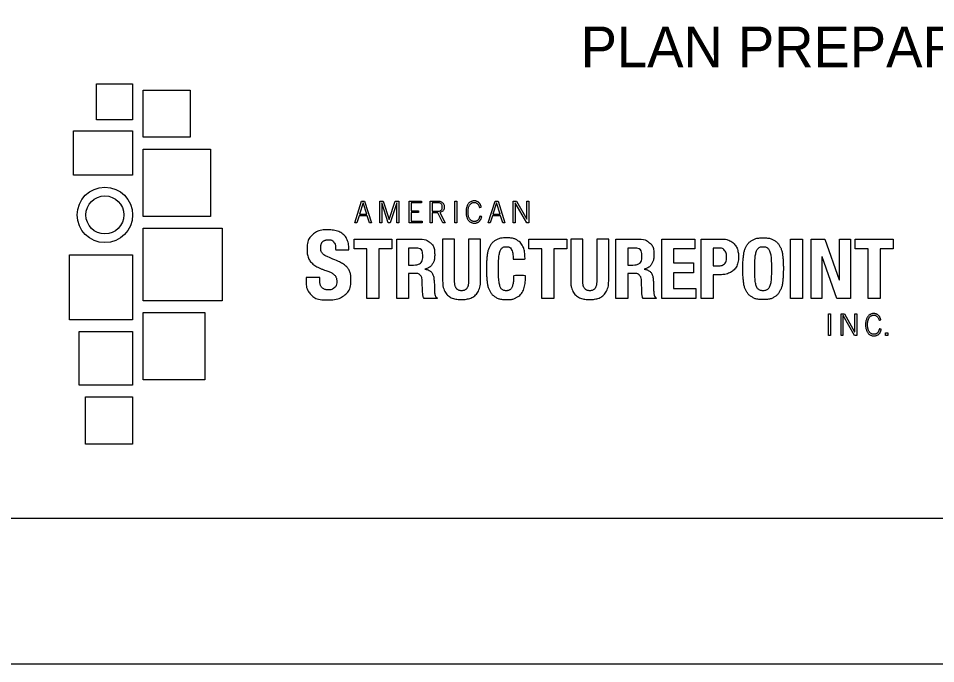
# Model space of a CAD drawing. Extents: x -21.9 to 47.3, y 14.1 to 48.7.
# Drawn here: x 1.676 to 4.831, y 26.733 to 28.955 of the extents above; entities that cross this region are included whole.
import ezdxf

# ---------------------------------------------------------------- set-up
doc = ezdxf.new("R2010")
doc.units = 0
for name, color, linetype in [('Default', 7, 'Continuous'), ('SH_Border', 7, 'Continuous'), ('SH_Cut_Line', 7, 'Continuous'), ('SH_Data', 7, 'Continuous'), ('SH_Text', 7, 'Continuous')]:
    doc.layers.add(name, color=color, linetype=linetype)

msp = doc.modelspace()

# ---------------------------------------------------------------- linework, layer by layer
at = {"layer": 'Default'}
for points in [[(1.944, 28.7301), (2.0687, 28.7301), (2.0687, 28.6054), (1.944, 28.6054)], [(2.1051, 28.7078), (2.2672, 28.7078), (2.2672, 28.5457), (2.1051, 28.5457)], [(1.8658, 28.5676), (2.0687, 28.5676), (2.0687, 28.4148), (1.8658, 28.4148)], [(2.1051, 28.5051), (2.3371, 28.5051), (2.3371, 28.2731), (2.1051, 28.2731)], [(2.1051, 28.2325), (2.3773, 28.2325), (2.3773, 27.983), (2.1051, 27.983)], [(1.8512, 28.1411), (2.0687, 28.1411), (2.0687, 27.9166), (1.8512, 27.9166)], [(2.1051, 27.9423), (2.3177, 27.9423), (2.3177, 27.7103), (2.1051, 27.7103)], [(1.8846, 27.8768), (2.0687, 27.8768), (2.0687, 27.6927), (1.8846, 27.6927)], [(1.9066, 27.6516), (2.0687, 27.6516), (2.0687, 27.4895), (1.9066, 27.4895)]]:
    msp.add_lwpolyline(points, close=True, dxfattribs=at)
for radius in [0.0954, 0.0654]:
    msp.add_circle((1.9733, 28.2783), radius, dxfattribs=at)
at = {"layer": 'SH_Border'}
msp.add_lwpolyline([(1.5, 48.2334), (33.5, 48.2334), (33.5, 27.2334), (1.5, 27.2334)], close=True, dxfattribs=at)
at = {"layer": 'SH_Cut_Line'}
msp.add_lwpolyline([(0, 26.7334), (34, 26.7334), (34, 48.7334), (0, 48.7334)], close=True, dxfattribs=at)
at = {"layer": 'SH_Data'}
for points in [[(2.8326, 28.2512), (2.8564, 28.3257), (2.8668, 28.3257), (2.8903, 28.2512), (2.8831, 28.2512), (2.8756, 28.2756), (2.8475, 28.2756), (2.8398, 28.2512), (2.8326, 28.2512)], [(2.8492, 28.2812), (2.8741, 28.2812), (2.8617, 28.3201), (2.8615, 28.3201), (2.8492, 28.2812)], [(2.9187, 28.2512), (2.9187, 28.3257), (2.9307, 28.3257), (2.9513, 28.2626), (2.9515, 28.2626), (2.9721, 28.3257), (2.9841, 28.3257), (2.9841, 28.2512), (2.9773, 28.2512), (2.9773, 28.3201), (2.9771, 28.3201), (2.9547, 28.2512), (2.9482, 28.2512), (2.9258, 28.3201), (2.9255, 28.3201), (2.9255, 28.2512), (2.9187, 28.2512)], [(3.02, 28.2512), (3.02, 28.3257), (3.0625, 28.3257), (3.0625, 28.32), (3.0268, 28.32), (3.0268, 28.2927), (3.0525, 28.2927), (3.0525, 28.2871), (3.0268, 28.2871), (3.0268, 28.2568), (3.0644, 28.2568), (3.0644, 28.2512), (3.02, 28.2512)], [(3.1254, 28.2865), (3.1436, 28.2512), (3.1362, 28.2512), (3.1189, 28.2852), (3.0996, 28.2852), (3.0996, 28.2512), (3.0928, 28.2512), (3.0928, 28.3257), (3.118, 28.3257)], [(3.0996, 28.32), (3.0996, 28.2908), (3.118, 28.2908)], [(3.118, 28.32), (3.0996, 28.32)], [(3.1777, 28.3257), (3.1845, 28.3257), (3.1845, 28.2512), (3.1777, 28.2512), (3.1777, 28.3257)], [(3.2918, 28.2512), (3.3157, 28.3257), (3.3261, 28.3257), (3.3496, 28.2512), (3.3423, 28.2512), (3.3348, 28.2756), (3.3067, 28.2756), (3.2991, 28.2512), (3.2918, 28.2512)], [(3.3084, 28.2812), (3.3333, 28.2812), (3.3209, 28.3201), (3.3207, 28.3201), (3.3084, 28.2812)], [(3.378, 28.3257), (3.3894, 28.3257), (3.4249, 28.2636), (3.4251, 28.2636), (3.4251, 28.3257), (3.4319, 28.3257), (3.4319, 28.2512), (3.4248, 28.2512), (3.385, 28.3201), (3.3847, 28.3201), (3.3847, 28.2512), (3.378, 28.2512), (3.378, 28.3257)], [(2.9607, 28.1949), (2.9607, 28.161), (2.916, 28.161), (2.916, 27.9907), (2.875, 27.9907), (2.875, 28.161), (2.8304, 28.161), (2.8304, 28.1949), (2.9607, 28.1949)], [(2.9771, 27.9907), (2.9771, 28.1949), (3.0534, 28.1949)], [(3.5622, 28.1949), (3.5622, 28.161), (3.5175, 28.161), (3.5175, 27.9907), (3.4765, 27.9907), (3.4765, 28.161), (3.4318, 28.161), (3.4318, 28.1949), (3.5622, 28.1949)], [(3.7311, 27.9907), (3.7311, 28.1949), (3.8074, 28.1949)], [(4.0029, 28.1949), (4.0029, 28.161), (3.9299, 28.161), (3.9299, 28.1133), (3.9986, 28.1133), (3.9986, 28.0794), (3.9299, 28.0794), (3.9299, 28.0246), (4.0058, 28.0246), (4.0058, 27.9907), (3.8889, 27.9907), (3.8889, 28.1949), (4.0029, 28.1949)], [(4.0251, 27.9907), (4.0251, 28.1949), (4.0971, 28.1949)], [(4.3319, 27.9907), (4.3319, 28.1949), (4.373, 28.1949), (4.373, 27.9907), (4.3319, 27.9907)], [(4.4499, 28.1949), (4.4997, 28.055), (4.5003, 28.055), (4.5003, 28.1949), (4.5379, 28.1949), (4.5379, 27.9907), (4.491, 27.9907), (4.4406, 28.1337), (4.4401, 28.1337), (4.4401, 27.9907), (4.4025, 27.9907), (4.4025, 28.1949), (4.4499, 28.1949)], [(4.6849, 28.1949), (4.6849, 28.161), (4.6402, 28.161), (4.6402, 27.9907), (4.5992, 27.9907), (4.5992, 28.161), (4.5546, 28.161), (4.5546, 28.1949), (4.6849, 28.1949)], [(3.0181, 28.1644), (3.0181, 28.1057), (3.0355, 28.1057)], [(3.0378, 28.1644), (3.0181, 28.1644)], [(3.7722, 28.1644), (3.7722, 28.1057), (3.7896, 28.1057)], [(3.7919, 28.1644), (3.7722, 28.1644)], [(4.0662, 28.1644), (4.0662, 28.1028), (4.0845, 28.1028)], [(4.0834, 28.1644), (4.0662, 28.1644)], [(3.0739, 28.0919), (3.0739, 28.0914)], [(3.828, 28.0919), (3.828, 28.0914)], [(3.0405, 28.077), (3.0181, 28.077), (3.0181, 27.9907), (2.9771, 27.9907)], [(3.7945, 28.077), (3.7722, 28.077), (3.7722, 27.9907), (3.7311, 27.9907)], [(4.0882, 28.0723), (4.0662, 28.0723), (4.0662, 27.9907), (4.0251, 27.9907)], [(3.0663, 28.0121), (3.0652, 28.0513)], [(3.8204, 28.0121), (3.8192, 28.0513)], [(3.1161, 27.9924), (3.1161, 27.9907), (3.0715, 27.9907)], [(3.8701, 27.9924), (3.8701, 27.9907), (3.8255, 27.9907)], [(4.4623, 27.9376), (4.4691, 27.9376), (4.4691, 27.8632), (4.4623, 27.8632), (4.4623, 27.9376)], [(4.5057, 27.9376), (4.5172, 27.9376), (4.5526, 27.8756), (4.5529, 27.8756), (4.5529, 27.9376), (4.5596, 27.9376), (4.5596, 27.8632), (4.5526, 27.8632), (4.5127, 27.9321), (4.5125, 27.9321), (4.5125, 27.8632), (4.5057, 27.8632), (4.5057, 27.9376)], [(4.6582, 27.8632), (4.6582, 27.8725), (4.667, 27.8725), (4.667, 27.8632), (4.6582, 27.8632)]]:
    msp.add_lwpolyline(points, dxfattribs=at)
for points in [[(3.118, 28.3257), (3.1253, 28.3257), (3.131, 28.3238), (3.1349, 28.3201), (3.1389, 28.3165), (3.1409, 28.3116), (3.1409, 28.3054), (3.1409, 28.3005), (3.1396, 28.2964), (3.1371, 28.2933), (3.1347, 28.2901), (3.1307, 28.2879), (3.1254, 28.2865)], [(3.118, 28.2908), (3.1229, 28.2908), (3.1268, 28.2921), (3.1297, 28.2947), (3.1326, 28.2973), (3.1341, 28.3008), (3.1341, 28.3054), (3.1341, 28.31), (3.1327, 28.3136), (3.13, 28.3162), (3.1274, 28.3188), (3.1233, 28.32), (3.118, 28.32)], [(3.2619, 28.3038), (3.2603, 28.3093), (3.258, 28.3135), (3.255, 28.3165), (3.2521, 28.3195), (3.2483, 28.321), (3.2438, 28.321), (3.2401, 28.321), (3.2369, 28.3202), (3.2342, 28.3185), (3.2316, 28.3168), (3.2294, 28.3145), (3.2276, 28.3115), (3.2259, 28.3086), (3.2246, 28.3051), (3.2238, 28.3011), (3.2229, 28.2972), (3.2225, 28.2929), (3.2225, 28.2884), (3.2225, 28.2838), (3.2229, 28.2796), (3.2238, 28.2756), (3.2246, 28.2716), (3.2259, 28.2682), (3.2277, 28.2652), (3.2295, 28.2623), (3.2318, 28.26), (3.2345, 28.2583), (3.2373, 28.2566), (3.2406, 28.2558), (3.2445, 28.2558), (3.2474, 28.2558), (3.25, 28.2563), (3.2521, 28.2572), (3.2541, 28.2582), (3.2559, 28.2596), (3.2574, 28.2612), (3.2588, 28.2629), (3.26, 28.2648), (3.2609, 28.267), (3.2618, 28.2692), (3.2626, 28.2715), (3.2632, 28.2739), (3.2632, 28.2739), (3.2696, 28.2728), (3.2696, 28.2728), (3.2689, 28.2695), (3.268, 28.2664), (3.2667, 28.2636), (3.2654, 28.2609), (3.2638, 28.2585), (3.2618, 28.2565), (3.2598, 28.2545), (3.2574, 28.2529), (3.2545, 28.2518), (3.2517, 28.2507), (3.2483, 28.2501), (3.2444, 28.2501), (3.2398, 28.2501), (3.2358, 28.2511), (3.2323, 28.2529), (3.2287, 28.2547), (3.2257, 28.2573), (3.2233, 28.2607), (3.2209, 28.264), (3.219, 28.268), (3.2177, 28.2727), (3.2164, 28.2774), (3.2157, 28.2826), (3.2157, 28.2884), (3.2157, 28.2941), (3.2164, 28.2994), (3.2177, 28.304), (3.219, 28.3087), (3.2209, 28.3127), (3.2233, 28.3161), (3.2257, 28.3195), (3.2287, 28.3221), (3.2323, 28.3239), (3.2358, 28.3257), (3.2398, 28.3266), (3.2444, 28.3266), (3.2477, 28.3266), (3.2506, 28.3261), (3.2532, 28.325), (3.2559, 28.3239), (3.2581, 28.3224), (3.2601, 28.3204), (3.2621, 28.3185), (3.2637, 28.3162), (3.265, 28.3136), (3.2663, 28.311), (3.2674, 28.3082), (3.2682, 28.3051), (3.2682, 28.3051), (3.2619, 28.3038), (3.2619, 28.3038)], [(2.7124, 28.0628), (2.7124, 28.0628), (2.7124, 28.056), (2.7124, 28.056), (2.7124, 28.0506), (2.7128, 28.0456), (2.7136, 28.0412), (2.7145, 28.0368), (2.7161, 28.033), (2.7185, 28.03), (2.7209, 28.027), (2.724, 28.0246), (2.7279, 28.0229), (2.7318, 28.0211), (2.7369, 28.0203), (2.7432, 28.0203), (2.7503, 28.0203), (2.7567, 28.0226), (2.7624, 28.0273), (2.7682, 28.0319), (2.771, 28.0391), (2.771, 28.0489), (2.771, 28.0541), (2.7703, 28.0585), (2.7689, 28.0623), (2.7675, 28.0661), (2.7652, 28.0695), (2.762, 28.0726), (2.7587, 28.0756), (2.7545, 28.0784), (2.7492, 28.0809), (2.7439, 28.0833), (2.7373, 28.0859), (2.7296, 28.0885), (2.7192, 28.0919), (2.7102, 28.0958), (2.7026, 28.1), (2.6951, 28.1042), (2.6888, 28.1091), (2.6837, 28.1145), (2.6786, 28.1199), (2.6749, 28.1262), (2.6725, 28.1333), (2.6701, 28.1405), (2.6689, 28.1489), (2.6689, 28.1587), (2.6689, 28.1814), (2.6753, 28.1984), (2.688, 28.2098), (2.7008, 28.2212), (2.7183, 28.2269), (2.7405, 28.2269), (2.7509, 28.2269), (2.7604, 28.2257), (2.7692, 28.2235), (2.7779, 28.2212), (2.7855, 28.2175), (2.7918, 28.2124), (2.7982, 28.2074), (2.8032, 28.2009), (2.8067, 28.193), (2.8103, 28.1851), (2.8121, 28.1756), (2.8121, 28.1646), (2.8121, 28.1646), (2.8121, 28.1581), (2.8121, 28.1581), (2.8121, 28.1581), (2.7672, 28.1581), (2.7672, 28.1581), (2.7672, 28.1692), (2.7653, 28.1776), (2.7614, 28.1836), (2.7576, 28.1895), (2.7511, 28.1925), (2.7421, 28.1925), (2.737, 28.1925), (2.7327, 28.1918), (2.7292, 28.1902), (2.7258, 28.1887), (2.723, 28.1867), (2.721, 28.1842), (2.719, 28.1817), (2.7176, 28.1789), (2.7168, 28.1756), (2.7161, 28.1724), (2.7157, 28.169), (2.7157, 28.1655), (2.7157, 28.1584), (2.7172, 28.1524), (2.7202, 28.1475), (2.7233, 28.1426), (2.7297, 28.1382), (2.7397, 28.134), (2.7397, 28.134), (2.7756, 28.1185), (2.7756, 28.1185), (2.7843, 28.1146), (2.7915, 28.1105), (2.7972, 28.1063), (2.8029, 28.1021), (2.8074, 28.0975), (2.8108, 28.0926), (2.8141, 28.0877), (2.8165, 28.0824), (2.8178, 28.0765), (2.8191, 28.0707), (2.8197, 28.0642), (2.8197, 28.0571), (2.8197, 28.0326), (2.8126, 28.0146), (2.7985, 28.0031), (2.7843, 27.9917), (2.7645, 27.9859), (2.7392, 27.9859), (2.7129, 27.9859), (2.694, 27.9918), (2.6826, 28.0036), (2.6713, 28.0154), (2.6656, 28.032), (2.6656, 28.0534), (2.6656, 28.0534), (2.6656, 28.0628), (2.6656, 28.0628), (2.6656, 28.0628), (2.7124, 28.0628), (2.7124, 28.0628)], [(3.0534, 28.1949), (3.0704, 28.1949), (3.0837, 28.1905), (3.0934, 28.1817), (3.103, 28.173), (3.1078, 28.1598), (3.1078, 28.1423), (3.1078, 28.1285), (3.1051, 28.1173), (3.0996, 28.1087), (3.0941, 28.1), (3.0855, 28.0944), (3.0739, 28.0919)], [(3.1764, 28.1949), (3.1764, 28.1949), (3.1764, 28.0528), (3.1764, 28.0528), (3.1764, 28.0477), (3.1767, 28.0429), (3.1774, 28.0387), (3.178, 28.0344), (3.1793, 28.0307), (3.1811, 28.0275), (3.1829, 28.0244), (3.1854, 28.0219), (3.1885, 28.0201), (3.1917, 28.0183), (3.1957, 28.0174), (3.2005, 28.0174), (3.2052, 28.0174), (3.2092, 28.0183), (3.2124, 28.0201), (3.2155, 28.0219), (3.218, 28.0244), (3.2198, 28.0275), (3.2216, 28.0307), (3.2229, 28.0344), (3.2235, 28.0387), (3.2242, 28.0429), (3.2245, 28.0477), (3.2245, 28.0528), (3.2245, 28.0528), (3.2245, 28.1949), (3.2245, 28.1949), (3.2245, 28.1949), (3.2656, 28.1949), (3.2656, 28.1949), (3.2656, 28.1949), (3.2656, 28.0526), (3.2656, 28.0526), (3.2656, 28.0396), (3.2638, 28.0289), (3.2602, 28.0204), (3.2565, 28.012), (3.2517, 28.0053), (3.2456, 28.0003), (3.2395, 27.9953), (3.2325, 27.9919), (3.2247, 27.9899), (3.2169, 27.9879), (3.2088, 27.9869), (3.2005, 27.9869), (3.1921, 27.9869), (3.184, 27.9877), (3.1762, 27.9895), (3.1684, 27.9912), (3.1614, 27.9944), (3.1553, 27.9993), (3.1492, 28.0042), (3.1444, 28.0108), (3.1408, 28.0193), (3.1371, 28.0278), (3.1353, 28.0389), (3.1353, 28.0526), (3.1353, 28.0526), (3.1353, 28.1949), (3.1353, 28.1949), (3.1353, 28.1949), (3.1764, 28.1949), (3.1764, 28.1949)], [(3.3776, 28.126), (3.3776, 28.1409), (3.3758, 28.1517), (3.3723, 28.1585), (3.3687, 28.1653), (3.3623, 28.1687), (3.3529, 28.1687), (3.3477, 28.1687), (3.3435, 28.1673), (3.3401, 28.1645), (3.3368, 28.1618), (3.3341, 28.1573), (3.3322, 28.1511), (3.3303, 28.1449), (3.3289, 28.1368), (3.3282, 28.1269), (3.3274, 28.1169), (3.327, 28.1046), (3.327, 28.0902), (3.327, 28.0748), (3.3276, 28.0623), (3.3286, 28.0528), (3.3297, 28.0433), (3.3313, 28.0359), (3.3335, 28.0307), (3.3357, 28.0255), (3.3385, 28.0219), (3.3419, 28.0201), (3.3453, 28.0183), (3.3491, 28.0174), (3.3536, 28.0174), (3.3572, 28.0174), (3.3606, 28.018), (3.3638, 28.0193), (3.367, 28.0205), (3.3697, 28.023), (3.372, 28.0267), (3.3743, 28.0304), (3.3761, 28.0357), (3.3775, 28.0425), (3.3788, 28.0492), (3.3795, 28.0582), (3.3795, 28.0692), (3.3795, 28.0692), (3.4206, 28.0692), (3.4206, 28.0692), (3.4206, 28.0582), (3.4197, 28.0477), (3.418, 28.0377), (3.4163, 28.0278), (3.4131, 28.0191), (3.4084, 28.0115), (3.4037, 28.0039), (3.3971, 27.9979), (3.3886, 27.9935), (3.3801, 27.9891), (3.3691, 27.9869), (3.3556, 27.9869), (3.3401, 27.9869), (3.3278, 27.9895), (3.3186, 27.9947), (3.3095, 28), (3.3025, 28.0073), (3.2976, 28.0166), (3.2927, 28.026), (3.2896, 28.0372), (3.2881, 28.0503), (3.2867, 28.0633), (3.286, 28.0776), (3.286, 28.093), (3.286, 28.1085), (3.2867, 28.1227), (3.2881, 28.1358), (3.2896, 28.1489), (3.2927, 28.1601), (3.2976, 28.1694), (3.3024, 28.1788), (3.3094, 28.1861), (3.3186, 28.1913), (3.3277, 28.1966), (3.34, 28.1992), (3.3555, 28.1992), (3.3701, 28.1992), (3.3817, 28.1968), (3.3902, 28.192), (3.3987, 28.1872), (3.405, 28.1811), (3.4092, 28.1737), (3.4134, 28.1663), (3.416, 28.1584), (3.4171, 28.1499), (3.4181, 28.1414), (3.4186, 28.1334), (3.4186, 28.126), (3.4186, 28.126), (3.3776, 28.126), (3.3776, 28.126)], [(3.6172, 28.1949), (3.6172, 28.1949), (3.6172, 28.0528), (3.6172, 28.0528), (3.6172, 28.0477), (3.6175, 28.0429), (3.6182, 28.0387), (3.6189, 28.0344), (3.6201, 28.0307), (3.6219, 28.0275), (3.6238, 28.0244), (3.6262, 28.0219), (3.6294, 28.0201), (3.6326, 28.0183), (3.6365, 28.0174), (3.6413, 28.0174), (3.6461, 28.0174), (3.6501, 28.0183), (3.6532, 28.0201), (3.6564, 28.0219), (3.6588, 28.0244), (3.6607, 28.0275), (3.6625, 28.0307), (3.6637, 28.0344), (3.6644, 28.0387), (3.6651, 28.0429), (3.6654, 28.0477), (3.6654, 28.0528), (3.6654, 28.0528), (3.6654, 28.1949), (3.6654, 28.1949), (3.6654, 28.1949), (3.7064, 28.1949), (3.7064, 28.1949), (3.7064, 28.1949), (3.7064, 28.0526), (3.7064, 28.0526), (3.7064, 28.0396), (3.7046, 28.0289), (3.701, 28.0204), (3.6974, 28.012), (3.6925, 28.0053), (3.6864, 28.0003), (3.6803, 27.9953), (3.6734, 27.9919), (3.6656, 27.9899), (3.6578, 27.9879), (3.6497, 27.9869), (3.6413, 27.9869), (3.6329, 27.9869), (3.6248, 27.9877), (3.617, 27.9895), (3.6092, 27.9912), (3.6023, 27.9944), (3.5962, 27.9993), (3.5901, 28.0042), (3.5852, 28.0108), (3.5816, 28.0193), (3.578, 28.0278), (3.5762, 28.0389), (3.5762, 28.0526), (3.5762, 28.0526), (3.5762, 28.1949), (3.5762, 28.1949), (3.5762, 28.1949), (3.6172, 28.1949), (3.6172, 28.1949)], [(3.8074, 28.1949), (3.8244, 28.1949), (3.8377, 28.1905), (3.8474, 28.1817), (3.8571, 28.173), (3.8619, 28.1598), (3.8619, 28.1423), (3.8619, 28.1285), (3.8591, 28.1173), (3.8536, 28.1087), (3.8481, 28.1), (3.8396, 28.0944), (3.828, 28.0919)], [(4.0971, 28.1949), (4.1075, 28.1949), (4.1163, 28.1931), (4.1235, 28.1896), (4.1306, 28.1861), (4.1364, 28.1815), (4.1407, 28.1757), (4.1451, 28.17), (4.1482, 28.1635), (4.1502, 28.1562), (4.1521, 28.1488), (4.153, 28.1414), (4.153, 28.1337), (4.153, 28.1231), (4.1514, 28.1139), (4.1483, 28.1061), (4.1452, 28.0984), (4.1408, 28.0921), (4.1352, 28.0871), (4.1295, 28.0822), (4.1227, 28.0785), (4.1147, 28.076), (4.1067, 28.0735), (4.0979, 28.0723), (4.0882, 28.0723)], [(4.168, 28.093), (4.168, 28.1085), (4.1687, 28.1227), (4.1701, 28.1358), (4.1716, 28.1489), (4.1747, 28.1601), (4.1796, 28.1694), (4.1845, 28.1788), (4.1915, 28.1861), (4.2007, 28.1913), (4.2098, 28.1966), (4.2222, 28.1992), (4.2377, 28.1992), (4.2531, 28.1992), (4.2655, 28.1966), (4.2746, 28.1913), (4.2838, 28.1861), (4.2908, 28.1788), (4.2957, 28.1694), (4.3006, 28.1601), (4.3037, 28.1489), (4.3052, 28.1358), (4.3066, 28.1227), (4.3073, 28.1085), (4.3073, 28.093), (4.3073, 28.0846), (4.3071, 28.0765), (4.3067, 28.0687)], [(3.0355, 28.1057), (3.0456, 28.1057), (3.0533, 28.108), (3.0587, 28.1127), (3.0641, 28.1173), (3.0668, 28.1251), (3.0668, 28.1362), (3.0668, 28.155), (3.0572, 28.1644), (3.0378, 28.1644)], [(3.7896, 28.1057), (3.7996, 28.1057), (3.8073, 28.108), (3.8127, 28.1127), (3.8181, 28.1173), (3.8208, 28.1251), (3.8208, 28.1362), (3.8208, 28.155), (3.8112, 28.1644), (3.7919, 28.1644)], [(4.0845, 28.1028), (4.0927, 28.1028), (4.0993, 28.1053), (4.1044, 28.1102), (4.1094, 28.1151), (4.112, 28.1228), (4.112, 28.1332), (4.112, 28.1432), (4.1098, 28.1509), (4.1054, 28.1563), (4.101, 28.1617), (4.0937, 28.1644), (4.0834, 28.1644)], [(4.209, 28.093), (4.209, 28.0793), (4.2094, 28.0677), (4.21, 28.0581), (4.2107, 28.0485), (4.2121, 28.0407), (4.2141, 28.0347), (4.2161, 28.0287), (4.219, 28.0243), (4.2228, 28.0216), (4.2265, 28.0188), (4.2315, 28.0174), (4.2377, 28.0174), (4.2438, 28.0174), (4.2488, 28.0188), (4.2525, 28.0216), (4.2563, 28.0243), (4.2592, 28.0287), (4.2612, 28.0347), (4.2632, 28.0407), (4.2646, 28.0485), (4.2653, 28.0581), (4.2659, 28.0677), (4.2663, 28.0793), (4.2663, 28.093), (4.2663, 28.1067), (4.2659, 28.1183), (4.2653, 28.1279), (4.2646, 28.1374), (4.2632, 28.1452), (4.2612, 28.1512), (4.2592, 28.1573), (4.2563, 28.1618), (4.2525, 28.1645), (4.2488, 28.1673), (4.2438, 28.1687), (4.2377, 28.1687), (4.2315, 28.1687), (4.2265, 28.1673), (4.2228, 28.1645), (4.219, 28.1618), (4.2161, 28.1573), (4.2141, 28.1512), (4.2121, 28.1452), (4.2107, 28.1374), (4.21, 28.1279), (4.2094, 28.1183), (4.209, 28.1067), (4.209, 28.093)], [(3.0739, 28.0914), (3.081, 28.0904), (3.0866, 28.0887), (3.0908, 28.0861), (3.095, 28.0835), (3.0983, 28.0798), (3.1007, 28.0749), (3.1031, 28.0701), (3.1047, 28.0639), (3.1055, 28.0565), (3.1062, 28.049), (3.1067, 28.0399), (3.1069, 28.029), (3.1071, 28.0181), (3.1077, 28.0099), (3.1087, 28.0041), (3.1098, 27.9984), (3.1122, 27.9945), (3.1161, 27.9924)], [(3.828, 28.0914), (3.835, 28.0904), (3.8407, 28.0887), (3.8449, 28.0861), (3.8491, 28.0835), (3.8524, 28.0798), (3.8548, 28.0749), (3.8571, 28.0701), (3.8587, 28.0639), (3.8595, 28.0565), (3.8603, 28.049), (3.8607, 28.0399), (3.8609, 28.029), (3.8611, 28.0181), (3.8617, 28.0099), (3.8628, 28.0041), (3.8638, 27.9984), (3.8663, 27.9945), (3.8701, 27.9924)], [(4.3067, 28.0687), (4.3063, 28.0623), (4.3058, 28.0562), (4.3052, 28.0503), (4.3037, 28.0372), (4.3006, 28.026), (4.2957, 28.0166), (4.2908, 28.0073), (4.2838, 28), (4.2746, 27.9947), (4.2655, 27.9895), (4.2531, 27.9869), (4.2377, 27.9869), (4.2222, 27.9869), (4.2098, 27.9895), (4.2007, 27.9947), (4.1915, 28), (4.1845, 28.0073), (4.1796, 28.0166), (4.1747, 28.026), (4.1716, 28.0372), (4.1701, 28.0503), (4.1687, 28.0633), (4.168, 28.0776), (4.168, 28.093)], [(3.0652, 28.0513), (3.0648, 28.0593), (3.0627, 28.0656), (3.0589, 28.0702), (3.0552, 28.0748), (3.049, 28.077), (3.0405, 28.077)], [(3.8192, 28.0513), (3.8188, 28.0593), (3.8167, 28.0656), (3.813, 28.0702), (3.8092, 28.0748), (3.803, 28.077), (3.7945, 28.077)], [(3.0715, 27.9907), (3.0694, 27.9935), (3.068, 27.9968), (3.0675, 28.0006), (3.0669, 28.0043), (3.0665, 28.0081), (3.0663, 28.0121)], [(3.8255, 27.9907), (3.8234, 27.9935), (3.8221, 27.9968), (3.8215, 28.0006), (3.8209, 28.0043), (3.8206, 28.0081), (3.8204, 28.0121)], [(4.6364, 27.9158), (4.6348, 27.9212), (4.6325, 27.9255), (4.6295, 27.9285), (4.6265, 27.9315), (4.6228, 27.933), (4.6183, 27.933), (4.6146, 27.933), (4.6114, 27.9321), (4.6087, 27.9305), (4.6061, 27.9288), (4.6039, 27.9264), (4.6021, 27.9235), (4.6004, 27.9206), (4.5991, 27.9171), (4.5983, 27.9131), (4.5974, 27.9091), (4.597, 27.9049), (4.597, 27.9004), (4.597, 27.8958), (4.5974, 27.8916), (4.5983, 27.8876), (4.5991, 27.8836), (4.6004, 27.8801), (4.6022, 27.8772), (4.604, 27.8742), (4.6063, 27.8719), (4.609, 27.8702), (4.6118, 27.8686), (4.6151, 27.8677), (4.619, 27.8677), (4.6219, 27.8677), (4.6245, 27.8682), (4.6266, 27.8692), (4.6286, 27.8702), (4.6304, 27.8715), (4.6319, 27.8732), (4.6333, 27.8748), (4.6345, 27.8768), (4.6354, 27.879), (4.6363, 27.8812), (4.6371, 27.8835), (4.6377, 27.8859), (4.6377, 27.8859), (4.6441, 27.8847), (4.6441, 27.8847), (4.6434, 27.8814), (4.6425, 27.8784), (4.6412, 27.8756), (4.6399, 27.8728), (4.6383, 27.8704), (4.6363, 27.8684), (4.6343, 27.8664), (4.6319, 27.8649), (4.629, 27.8638), (4.6262, 27.8627), (4.6228, 27.8621), (4.6189, 27.8621), (4.6143, 27.8621), (4.6103, 27.863), (4.6068, 27.8648), (4.6032, 27.8667), (4.6002, 27.8693), (4.5978, 27.8726), (4.5954, 27.876), (4.5935, 27.88), (4.5922, 27.8847), (4.5909, 27.8894), (4.5902, 27.8946), (4.5902, 27.9004), (4.5902, 27.9061), (4.5909, 27.9113), (4.5922, 27.916), (4.5935, 27.9207), (4.5954, 27.9247), (4.5978, 27.9281), (4.6002, 27.9314), (4.6032, 27.934), (4.6068, 27.9359), (4.6103, 27.9377), (4.6143, 27.9386), (4.6189, 27.9386), (4.6222, 27.9386), (4.6251, 27.938), (4.6277, 27.9369), (4.6303, 27.9358), (4.6326, 27.9343), (4.6346, 27.9324), (4.6365, 27.9305), (4.6382, 27.9282), (4.6395, 27.9256), (4.6408, 27.9229), (4.6419, 27.9201), (4.6427, 27.9171), (4.6427, 27.9171), (4.6364, 27.9158), (4.6364, 27.9158)]]:
    msp.add_open_spline(points, degree=3, dxfattribs=at)

# ---------------------------------------------------------------- texts
at = {"layer": 'SH_Text'}
msp.add_text('PLAN PREPARED BY:', height=0.14, dxfattribs=at).set_placement((3.61, 28.7868))

doc.saveas('drawing.dxf')
